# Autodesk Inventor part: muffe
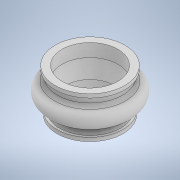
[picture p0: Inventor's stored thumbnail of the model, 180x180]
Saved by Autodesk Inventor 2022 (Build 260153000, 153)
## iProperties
Created: 2022-08
Part Number: muffe
Material: Generisch
Document SubType Name: Modeling
Designer: Basti
Density: 1 g/cm^3
Appearance: Vorgabe
Author: Basti
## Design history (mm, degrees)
sketch "Skizze1"
  geometry: L1 (0, 46.756)-(0, -29.563); L2 (-18.75, 23)-(-15, 23); L3 (-15, 23)-(-15, 16); L4 (-15, 16)-(-13.25, 7); L5 (-13.25, 7)-(-13.25, 0); L6 (-13.25, 0)-(-17.75, 0); L7 (-17.75, 0)-(-17.75, 2); L8 (-17.75, 2)-(-16.5, 2); L9 (-16.5, 2)-(-16.5, 7); L10 (-18.75, 23)-(-18.75, 21); L11 (-18.75, 21)-(-17.5, 21); L12 (-17.5, 21)-(-17.5, 16); L13 (-22.5, 15.171)-(-22.5, 5.718); L14 (-16.5, 7)-(-20.684, 7.738); A1 r 4.611 centre (-17.889, 11.405) between (-17.5, 16) and (-20.684, 7.738); 1 further point
  constraints: 28 end point, 7 perpendicular, 3 vertical, 2 horizontal alignment, 2 point on circle, 2 point on line, 1 centre point, 1 horizontal, 1 parallel, 1 tangent
  dimensions: "d0" = 35.5 diameter of L7 L1; "d1" = 26.5 diameter of L5 L1; "d2" = 33 diameter of L9 L1; "d3" = 2 distance between parallel lines of L6 L8; "d4" = 7 distance from line of L2 L12.end; "d5" = 2 distance between parallel lines of L2 L11; "d6" = 30 diameter of L3 L1; "d7" = 35 diameter of L12 L1; "d8" = 37.5 diameter of L10 L1; "d10" = 9 vertical distance of L9.end L12.end; "d11" = 7 distance from line of L9.end L6; "d12" = 23 distance between parallel lines of L2 L6 (derived); "d14" = 45 diameter of L13 L1; "d15" = 100 deg angle of L14 L9; "d16" = 4.18382 horizontal distance of L9.end L14.end
revolve "Umdrehung1" sketch "Skizze1" stored, may be unused: angle "d17" = 90 deg
fillet "Rundung1" dims "d18" = 1.5
fillet "Rundung2" dims "d19" = 2
node "Volumenkörper1"
